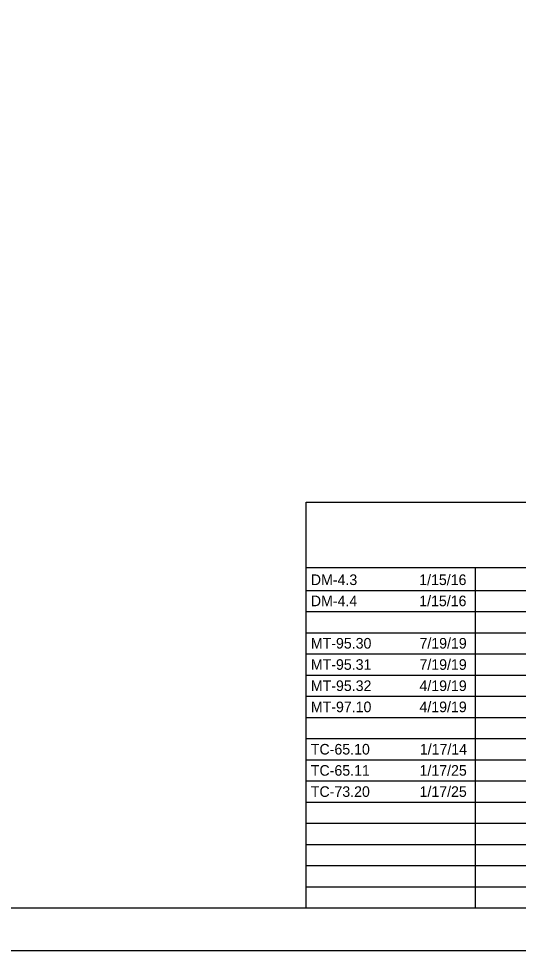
# Model space of a CAD drawing. Extents: x 0 to 34, y 0 to 22.
# Drawn here: x 6.75 to 12.66, y 0 to 11 of the extents above; entities that cross this region are included whole.
import ezdxf

# ---------------------------------------------------------------- set-up
doc = ezdxf.new("R2010")
doc.units = 0
for name, color, linetype in [('SH_Border', 7, 'Continuous'), ('SH_Cut_Line', 7, 'Continuous'), ('SH_Data', 7, 'Continuous'), ('SH_Text', 7, 'Continuous')]:
    doc.layers.add(name, color=color, linetype=linetype)

msp = doc.modelspace()

# ---------------------------------------------------------------- linework, layer by layer
at = {"layer": 'SH_Border'}
msp.add_lwpolyline([(1.5, 21.5), (33.5, 21.5), (33.5, 0.5), (1.5, 0.5)], close=True, dxfattribs=at)
msp.add_lwpolyline([(32, 0.5), (1.5, 0.5), (1.5, 21.5), (32, 21.5)], dxfattribs=at)
at = {"layer": 'SH_Cut_Line'}
msp.add_lwpolyline([(0, 0), (34, 0), (34, 22), (0, 22)], close=True, dxfattribs=at)
at = {"layer": 'SH_Data'}
for p, q in [((10.15, 5.292), (23.6, 5.292)), ((10.15, 0.5), (10.15, 5.292)), ((10.15, 4.521), (23.6, 4.521)), ((12.15, 0.5), (12.15, 4.521)), ((10.15, 4.25), (23.6, 4.25)), ((10.15, 4), (23.6, 4)), ((10.15, 3.75), (23.6, 3.75)), ((10.15, 3.5), (23.6, 3.5)), ((10.15, 3.25), (23.6, 3.25)), ((10.15, 3), (23.6, 3)), ((10.15, 2.75), (23.6, 2.75)), ((10.15, 2.5), (23.6, 2.5)), ((10.15, 2.25), (23.6, 2.25)), ((10.15, 2), (23.6, 2)), ((10.15, 1.75), (23.6, 1.75)), ((10.15, 1.5), (23.6, 1.5)), ((10.15, 1.25), (23.6, 1.25)), ((10.15, 1), (23.6, 1)), ((10.15, 0.75), (23.6, 0.75))]:
    msp.add_line(p, q, dxfattribs=at)

# ---------------------------------------------------------------- texts
at = {"layer": 'SH_Text'}
for s, p in [('DM-4.3', (10.205, 4.313)), ('1/15/16', (11.485, 4.313)), ('DM-4.4', (10.205, 4.063)), ('1/15/16', (11.485, 4.063)), ('MT-95.30', (10.205, 3.563)), ('7/19/19', (11.488, 3.563)), ('MT-95.31', (10.205, 3.312)), ('7/19/19', (11.488, 3.312)), ('4/19/19', (11.488, 3.062)), ('MT-95.32', (10.205, 3.062)), ('MT-97.10', (10.205, 2.812)), ('4/19/19', (11.488, 2.812)), ('TC-65.10', (10.205, 2.312)), ('1/17/14', (11.492, 2.312)), ('TC-65.11', (10.205, 2.062)), ('1/17/25', (11.489, 2.062)), ('TC-73.20', (10.205, 1.812)), ('1/17/25', (11.489, 1.812))]:
    msp.add_text(s, height=0.125, dxfattribs=at).set_placement(p)

doc.saveas('drawing.dxf')
